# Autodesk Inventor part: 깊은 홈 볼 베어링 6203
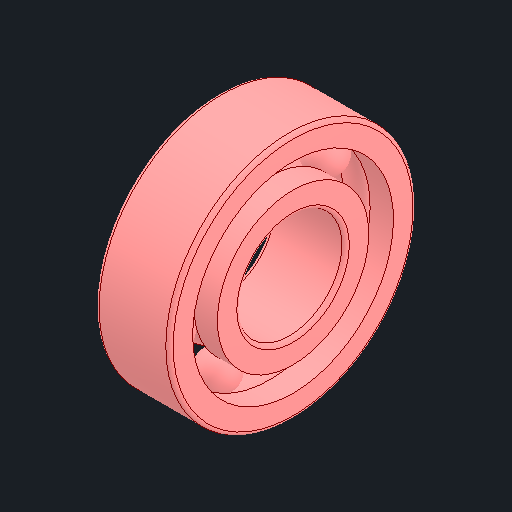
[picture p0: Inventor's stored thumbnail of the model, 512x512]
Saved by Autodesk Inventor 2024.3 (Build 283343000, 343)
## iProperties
Created: 2025-03
Part Number: 깊은 홈 볼 베어링 6203
Material: 강철, 연강
Description: 깊은 그루브 볼 베어링
Document SubType Name: Modeling
Designer: user
Density: 7.85 g/cm^3
Appearance: 기본값
Author: jhkim
Sending System: Autodesk Inventor 2025
Preprocessor: ST-DEVELOPER v20
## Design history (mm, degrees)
feature "Solid1"
feature "Solid1:1"
feature "Solid1:2"
feature "Solid1:3"
feature "Solid1:4"
feature "Solid1:5"
feature "Solid1:6"
feature "Solid1:7"
feature "Solid1:8"
node "솔리드1"
node "솔리드2"
node "솔리드3"
node "솔리드4"
node "솔리드5"
node "솔리드6"
node "솔리드7"
node "솔리드8"
node "솔리드9"
